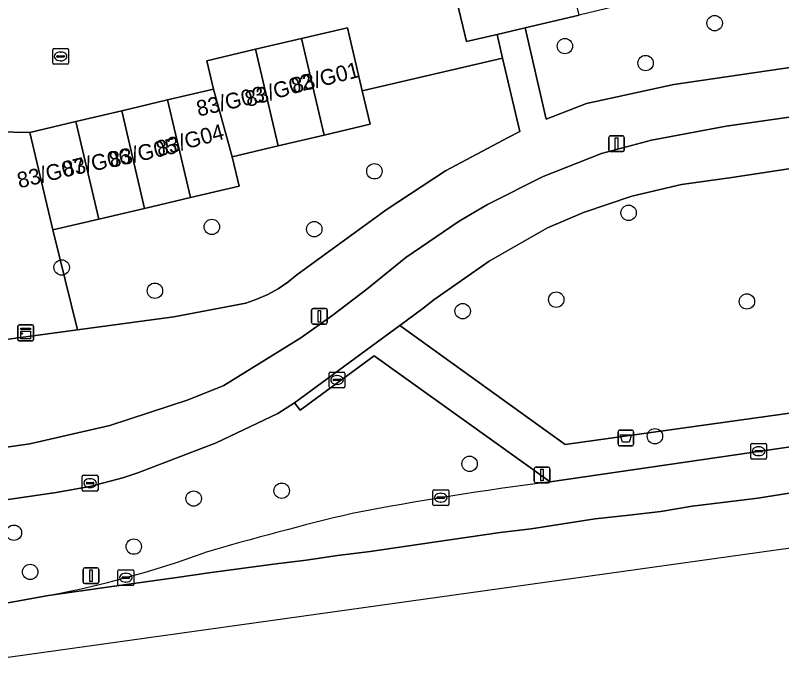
# Model space of a CAD drawing. Extents: x 157793 to 159380, y 380877 to 382313.
# Drawn here: x 158660.5 to 158709.17, y 381159.24 to 381200.11 of the extents above; entities that cross this region are included whole.
import ezdxf

# ---------------------------------------------------------------- set-up
doc = ezdxf.new("R2010")
doc.units = 0
for name, color, linetype in [('IMGEO_Afvalbak', 7, 'Continuous'), ('IMGEO_Berm_groen', 7, 'Continuous'), ('IMGEO_Boom', 7, 'Continuous'), ('IMGEO_Fietspad_gesloten', 7, 'Continuous'), ('IMGEO_Groenvoorziening', 7, 'Continuous'), ('IMGEO_Kast', 7, 'Continuous'), ('IMGEO_Kolk', 7, 'Continuous'), ('IMGEO_Lichtmast', 7, 'Continuous'), ('IMGEO_Pand', 7, 'Continuous'), ('IMGEO_Pand_nummerreeks', 7, 'Continuous'), ('IMGEO_Rijbaan_lokaal_open', 7, 'Continuous'), ('IMGEO_Rijbaan_regionaal_gesloten', 7, 'Continuous'), ('IMGEO_Voetpad_open', 7, 'Continuous')]:
    doc.layers.add(name, color=color, linetype=linetype)

msp = doc.modelspace()

# ---------------------------------------------------------------- linework, layer by layer
at = {"layer": 'IMGEO_Afvalbak'}
for p, q in [((158698.782, 381172.854), (158698.782, 381173.654)), ((158698.782, 381173.654), (158698.782, 381172.854)), ((158698.882, 381173.754), (158699.672, 381173.754)), ((158699.672, 381173.754), (158698.882, 381173.754)), ((158699.772, 381173.654), (158699.772, 381172.854)), ((158699.772, 381172.854), (158699.772, 381173.654)), ((158699.672, 381172.754), (158698.882, 381172.754)), ((158698.882, 381172.754), (158699.672, 381172.754))]:
    msp.add_line(p, q, dxfattribs=at)
msp.add_lwpolyline([(158698.925, 381173.468), (158699.629, 381173.468), (158699.48, 381172.998), (158699.074, 381172.998), (158698.925, 381173.468)], dxfattribs=at)
for centre, start, end in [((158698.882, 381173.654), 90, 180), ((158698.882, 381173.654), 90, 180), ((158699.672, 381173.654), 0, 90), ((158699.672, 381173.654), 360, 90), ((158698.882, 381172.854), 180, 270), ((158698.882, 381172.854), 180, 270), ((158699.672, 381172.854), 270, 0), ((158699.672, 381172.854), 270, 0)]:
    msp.add_arc(centre, 0.1, start, end, dxfattribs=at)
at = {"layer": 'IMGEO_Berm_groen'}
msp.add_lwpolyline([(158728.029, 381190.698), (158727.696, 381193.095), (158726.473, 381192.91), (158724.645, 381192.633), (158706.01, 381189.815), (158702.809, 381189.355), (158699.661, 381188.611), (158696.593, 381187.589), (158694.298, 381186.617), (158690.589, 381184.484), (158687.086, 381182.027), (158686.392, 381181.483), (158684.914, 381180.398), (158695.427, 381172.833), (158714.686, 381175.526), (158714.959, 381175.368), (158715.054, 381174.92), (158722.082, 381175.922), (158725.926, 381180.89), (158729.328, 381181.351)], close=True, dxfattribs=at)
msp.add_lwpolyline([(158694.468, 381170.476), (158683.301, 381178.47), (158678.595, 381175.016), (158678.24, 381175.5), (158677.179, 381174.821), (158673.253, 381172.947), (158668.276, 381171.049), (158667.33, 381170.729), (158665.236, 381170.171), (158663.101, 381169.802), (158659.302, 381169.246), (158656.946, 381168.934), (158658.382, 381162.481), (158662.608, 381163.25)], dxfattribs=at)
for centre, radius, start, end in [((158720.591, 380966.633), 205.51, 97.3027, 100.85619), ((158731.516, 380962.484), 211.876, 103.54752, 106.17714), ((158651.234, 381223.831), 61.639, 280.63332, 290.16825)]:
    msp.add_arc(centre, radius, start, end, dxfattribs=at)
at = {"layer": 'IMGEO_Boom'}
for centre in [(158704.916, 381199.608), (158695.405, 381198.152), (158700.531, 381197.076), (158683.305, 381190.2), (158699.453, 381187.561), (158672.981, 381186.667), (158679.489, 381186.524), (158663.444, 381184.088), (158669.368, 381182.611), (158694.857, 381182.046), (158706.967, 381181.931), (158688.913, 381181.312), (158701.123, 381173.369), (158689.352, 381171.613), (158677.417, 381169.907), (158671.828, 381169.41), (158660.412, 381167.239), (158668.023, 381166.356), (158661.443, 381164.75)]:
    msp.add_circle(centre, 0.489, dxfattribs=at)
at = {"layer": 'IMGEO_Fietspad_gesloten'}
for points in [[(158732.23, 381196.863), (158705.649, 381193.06), (158700.9, 381192.169), (158697.733, 381191.325), (158694.035, 381189.869), (158690.482, 381188.089), (158688.7, 381187.039), (158685.304, 381184.715), (158682.826, 381182.712), (158681.128, 381181.421), (158680.599, 381181.023), (158678.633, 381179.627), (158673.739, 381176.601), (158671.476, 381175.689), (158666.512, 381174.058), (158661.423, 381172.877), (158656.232, 381172.144)], [(158659.302, 381169.246), (158663.101, 381169.802), (158665.236, 381170.171), (158667.33, 381170.729), (158668.276, 381171.049), (158673.253, 381172.947), (158677.179, 381174.821), (158678.24, 381175.5), (158682.788, 381178.838), (158684.914, 381180.398), (158686.392, 381181.483), (158687.086, 381182.027), (158690.589, 381184.484), (158694.298, 381186.617), (158696.593, 381187.589), (158699.661, 381188.611), (158702.809, 381189.355), (158706.01, 381189.815), (158724.645, 381192.633)]]:
    msp.add_lwpolyline(points, dxfattribs=at)
at = {"layer": 'IMGEO_Groenvoorziening'}
msp.add_lwpolyline([(158639.885, 381225.076), (158650.525, 381180.723), (158651.559, 381180.924), (158651.726, 381180.142), (158651.334, 381180.059), (158651.501, 381179.276), (158650.903, 381179.149), (158651.005, 381178.722), (158651.08, 381178.369), (158659.877, 381179.488), (158660.066, 381179.544), (158664.457, 381180.133), (158662.884, 381186.473), (158661.425, 381192.673), (158659.32, 381192.701), (158657.702, 381194.386), (158650.313, 381190.665), (158650.687, 381191.52), (158651.061, 381193.016), (158651.115, 381194.557), (158651.021, 381195.323), (158651.443, 381196.528), (158651.748, 381198.396), (158651.658, 381200.286)], dxfattribs=at)
for points in [[(158722.998, 381202.115), (158718.804, 381201.132), (158717.835, 381205.337), (158696.306, 381200.119), (158692.877, 381199.313), (158694.205, 381193.509), (158696.771, 381194.499), (158702.33, 381195.721), (158723.738, 381198.857)], [(158687.83, 381190.226), (158691.806, 381192.354), (158692.538, 381192.731), (158691.446, 381197.396), (158682.534, 381195.303), (158683.032, 381193.188), (158680.113, 381192.501), (158677.195, 381191.815), (158674.276, 381191.128), (158674.717, 381189.256), (158671.631, 381188.53), (158668.715, 381187.844), (158665.799, 381187.159), (158662.884, 381186.473), (158664.457, 381180.133), (158670.578, 381180.953), (158675.134, 381181.831), (158675.845, 381182.071), (158676.531, 381182.374), (158677.188, 381182.737), (158677.809, 381183.157), (158678.387, 381183.628), (158683.743, 381187.521), (158684.06, 381187.752)]]:
    msp.add_lwpolyline(points, close=True, dxfattribs=at)
at = {"layer": 'IMGEO_Kast'}
for p, q in [((158660.66, 381179.511), (158660.66, 381180.352)), ((158660.66, 381180.352), (158660.66, 381179.511)), ((158660.735, 381180.436), (158661.576, 381180.436)), ((158661.576, 381180.436), (158660.735, 381180.436)), ((158661.66, 381180.361), (158661.66, 381179.52)), ((158661.66, 381179.52), (158661.66, 381180.361)), ((158661.585, 381179.436), (158660.744, 381179.436)), ((158660.744, 381179.436), (158661.585, 381179.436))]:
    msp.add_line(p, q, dxfattribs=at)
for points in [[(158660.855, 381180.226), (158661.455, 381180.226), (158661.455, 381180.141), (158660.855, 381180.141), (158660.855, 381180.226)], [(158660.855, 381180.051), (158661.455, 381180.051), (158661.455, 381179.562), (158660.855, 381179.562), (158660.855, 381180.051)]]:
    msp.add_lwpolyline(points, dxfattribs=at)
msp.add_circle((158660.939, 381179.9), 0.0377, dxfattribs=at)
for centre, start, end in [((158660.738, 381180.358), 92.4484, 184.2845), ((158660.738, 381180.358), 92.4484, 184.2845), ((158661.582, 381180.358), 2.4484, 94.2845), ((158661.582, 381180.358), 2.4484, 94.2845), ((158660.738, 381179.514), 182.4484, 274.2845), ((158660.738, 381179.514), 182.4484, 274.2845), ((158661.582, 381179.514), 272.4484, 4.2845), ((158661.582, 381179.514), 272.4484, 4.2845)]:
    msp.add_arc(centre, 0.0779, start, end, dxfattribs=at)
at = {"layer": 'IMGEO_Kolk'}
for p, q in [((158662.875, 381197.071), (158662.875, 381197.923)), ((158662.95, 381197.997), (158663.802, 381197.997)), ((158663.363, 381197.777), (158663.388, 381197.777)), ((158663.876, 381197.923), (158663.876, 381197.071)), ((158663.134, 381197.491), (158663.134, 381197.503)), ((158663.572, 381197.454), (158663.174, 381197.454)), ((158663.177, 381197.54), (158663.575, 381197.54)), ((158663.386, 381197.217), (158663.361, 381197.217)), ((158663.618, 381197.503), (158663.618, 381197.491)), ((158663.802, 381196.997), (158662.95, 381196.997)), ((158680.431, 381176.516), (158680.431, 381177.368)), ((158680.506, 381177.442), (158681.358, 381177.442)), ((158680.919, 381177.222), (158680.944, 381177.222)), ((158681.432, 381177.368), (158681.432, 381176.516)), ((158680.69, 381176.936), (158680.69, 381176.948)), ((158681.128, 381176.899), (158680.73, 381176.899)), ((158680.733, 381176.985), (158681.131, 381176.985)), ((158681.174, 381176.948), (158681.174, 381176.936)), ((158681.358, 381176.442), (158680.506, 381176.442)), ((158680.942, 381176.662), (158680.917, 381176.662)), ((158707.214, 381171.99), (158707.214, 381172.842)), ((158707.289, 381172.916), (158708.141, 381172.916)), ((158708.215, 381172.842), (158708.215, 381171.99)), ((158707.473, 381172.41), (158707.473, 381172.422)), ((158707.911, 381172.373), (158707.513, 381172.373)), ((158707.516, 381172.459), (158707.914, 381172.459)), ((158707.702, 381172.696), (158707.727, 381172.696)), ((158707.957, 381172.422), (158707.957, 381172.41)), ((158708.141, 381171.916), (158707.289, 381171.916)), ((158707.725, 381172.136), (158707.7, 381172.136)), ((158664.826, 381170.888), (158665.678, 381170.888)), ((158664.751, 381169.962), (158664.751, 381170.814)), ((158665.053, 381170.431), (158665.451, 381170.431)), ((158665.239, 381170.668), (158665.264, 381170.668)), ((158665.752, 381170.814), (158665.752, 381169.962)), ((158665.01, 381170.382), (158665.01, 381170.394)), ((158665.448, 381170.345), (158665.05, 381170.345)), ((158665.262, 381170.108), (158665.237, 381170.108)), ((158665.494, 381170.394), (158665.494, 381170.382)), ((158687.098, 381169.966), (158687.95, 381169.966)), ((158665.678, 381169.888), (158664.826, 381169.888)), ((158687.023, 381169.04), (158687.023, 381169.892)), ((158687.282, 381169.46), (158687.282, 381169.472)), ((158687.325, 381169.509), (158687.723, 381169.509)), ((158687.511, 381169.746), (158687.536, 381169.746)), ((158687.766, 381169.472), (158687.766, 381169.46)), ((158688.024, 381169.892), (158688.024, 381169.04)), ((158687.95, 381168.966), (158687.098, 381168.966)), ((158687.72, 381169.423), (158687.322, 381169.423)), ((158687.534, 381169.186), (158687.509, 381169.186)), ((158667.018, 381163.957), (158667.018, 381164.809)), ((158667.093, 381164.883), (158667.945, 381164.883)), ((158667.506, 381164.663), (158667.531, 381164.663)), ((158668.019, 381164.809), (158668.019, 381163.957)), ((158667.277, 381164.377), (158667.277, 381164.389)), ((158667.715, 381164.34), (158667.317, 381164.34)), ((158667.32, 381164.426), (158667.718, 381164.426)), ((158667.529, 381164.103), (158667.504, 381164.103)), ((158667.761, 381164.389), (158667.761, 381164.377)), ((158667.945, 381163.883), (158667.093, 381163.883))]:
    msp.add_line(p, q, dxfattribs=at)
for points in [[(158662.875, 381197.071), (158662.875, 381197.923)], [(158662.95, 381197.997), (158663.802, 381197.997)], [(158663.876, 381197.923), (158663.876, 381197.071)], [(158663.802, 381196.997), (158662.95, 381196.997)], [(158680.431, 381176.516), (158680.431, 381177.368)], [(158680.506, 381177.442), (158681.358, 381177.442)], [(158681.432, 381177.368), (158681.432, 381176.516)], [(158681.358, 381176.442), (158680.506, 381176.442)], [(158707.214, 381171.99), (158707.214, 381172.842)], [(158707.289, 381172.916), (158708.141, 381172.916)], [(158708.215, 381172.842), (158708.215, 381171.99)], [(158708.141, 381171.916), (158707.289, 381171.916)], [(158664.826, 381170.888), (158665.678, 381170.888)], [(158664.751, 381169.962), (158664.751, 381170.814)], [(158665.752, 381170.814), (158665.752, 381169.962)], [(158687.098, 381169.966), (158687.95, 381169.966)], [(158665.678, 381169.888), (158664.826, 381169.888)], [(158687.023, 381169.04), (158687.023, 381169.892)], [(158688.024, 381169.892), (158688.024, 381169.04)], [(158687.95, 381168.966), (158687.098, 381168.966)], [(158667.018, 381163.957), (158667.018, 381164.809)], [(158667.093, 381164.883), (158667.945, 381164.883)], [(158668.019, 381164.809), (158668.019, 381163.957)], [(158667.945, 381163.883), (158667.093, 381163.883)]]:
    msp.add_lwpolyline(points, dxfattribs=at)
for centre, radius, start, end in [((158662.952, 381197.921), 0.0765, 91.552, 178.448), ((158662.952, 381197.921), 0.0765, 91.552, 178.448), ((158663.8, 381197.921), 0.0765, 1.552, 88.448), ((158663.8, 381197.921), 0.0765, 1.552, 88.448), ((158663.174, 381197.5), 0.0403, 85.8775, 175.7526), ((158663.171, 381197.49), 0.0366, 178.938, 274.7102), ((158663.575, 381197.497), 0.043, 264.8664, 352.4533), ((158663.579, 381197.502), 0.0386, 1.7309, 96.639), ((158662.952, 381197.073), 0.0765, 181.552, 268.448), ((158662.952, 381197.073), 0.0765, 181.552, 268.448), ((158663.8, 381197.073), 0.0765, 271.552, 358.448), ((158663.8, 381197.073), 0.0765, 271.552, 358.448), ((158680.508, 381177.366), 0.0765, 91.552, 178.448), ((158680.508, 381177.366), 0.0765, 91.552, 178.448), ((158681.356, 381177.366), 0.0765, 1.552, 88.448), ((158681.356, 381177.366), 0.0765, 1.552, 88.448), ((158680.73, 381176.945), 0.0403, 85.8775, 175.7526), ((158680.727, 381176.935), 0.0366, 178.938, 274.7102), ((158681.131, 381176.942), 0.043, 264.8664, 352.4533), ((158681.135, 381176.947), 0.0386, 1.7309, 96.639), ((158680.508, 381176.518), 0.0765, 181.552, 268.448), ((158680.508, 381176.518), 0.0765, 181.552, 268.448), ((158681.356, 381176.518), 0.0765, 271.552, 358.448), ((158681.356, 381176.518), 0.0765, 271.552, 358.448), ((158707.291, 381172.84), 0.0765, 91.552, 178.448), ((158707.291, 381172.84), 0.0765, 91.552, 178.448), ((158708.139, 381172.84), 0.0765, 1.552, 88.448), ((158708.139, 381172.84), 0.0765, 1.552, 88.448), ((158707.513, 381172.419), 0.0403, 85.8775, 175.7526), ((158707.51, 381172.409), 0.0366, 178.938, 274.7102), ((158707.914, 381172.416), 0.043, 264.8664, 352.4533), ((158707.918, 381172.421), 0.0386, 1.7309, 96.639), ((158707.291, 381171.992), 0.0765, 181.552, 268.448), ((158707.291, 381171.992), 0.0765, 181.552, 268.448), ((158708.139, 381171.992), 0.0765, 271.552, 358.448), ((158708.139, 381171.992), 0.0765, 271.552, 358.448), ((158664.828, 381170.812), 0.0765, 91.552, 178.448), ((158664.828, 381170.812), 0.0765, 91.552, 178.448), ((158665.676, 381170.812), 0.0765, 1.552, 88.448), ((158665.676, 381170.812), 0.0765, 1.552, 88.448), ((158665.05, 381170.391), 0.0403, 85.8775, 175.7526), ((158665.455, 381170.393), 0.0386, 1.7309, 96.639), ((158664.828, 381169.964), 0.0765, 181.552, 268.448), ((158664.828, 381169.964), 0.0765, 181.552, 268.448), ((158665.047, 381170.381), 0.0366, 178.938, 274.7102), ((158665.451, 381170.388), 0.043, 264.8664, 352.4533), ((158665.676, 381169.964), 0.0765, 271.552, 358.448), ((158665.676, 381169.964), 0.0765, 271.552, 358.448), ((158687.1, 381169.89), 0.0765, 91.552, 178.448), ((158687.1, 381169.89), 0.0765, 91.552, 178.448), ((158687.948, 381169.89), 0.0765, 1.552, 88.448), ((158687.948, 381169.89), 0.0765, 1.552, 88.448), ((158687.322, 381169.469), 0.0403, 85.8775, 175.7526), ((158687.319, 381169.459), 0.0366, 178.938, 274.7102), ((158687.723, 381169.466), 0.043, 264.8664, 352.4533), ((158687.727, 381169.471), 0.0386, 1.7309, 96.639), ((158687.1, 381169.042), 0.0765, 181.552, 268.448), ((158687.1, 381169.042), 0.0765, 181.552, 268.448), ((158687.948, 381169.042), 0.0765, 271.552, 358.448), ((158687.948, 381169.042), 0.0765, 271.552, 358.448), ((158667.095, 381164.807), 0.0765, 91.552, 178.448), ((158667.095, 381164.807), 0.0765, 91.552, 178.448), ((158667.943, 381164.807), 0.0765, 1.552, 88.448), ((158667.943, 381164.807), 0.0765, 1.552, 88.448), ((158667.317, 381164.386), 0.0403, 85.8775, 175.7526), ((158667.314, 381164.376), 0.0366, 178.938, 274.7102), ((158667.718, 381164.383), 0.043, 264.8664, 352.4533), ((158667.722, 381164.388), 0.0386, 1.7309, 96.639), ((158667.095, 381163.959), 0.0765, 181.552, 268.448), ((158667.095, 381163.959), 0.0765, 181.552, 268.448), ((158667.943, 381163.959), 0.0765, 271.552, 358.448), ((158667.943, 381163.959), 0.0765, 271.552, 358.448)]:
    msp.add_arc(centre, radius, start, end, dxfattribs=at)
for centre, major_axis, ratio, start_param, end_param in [((158663.362, 381197.497), (-0.387, 0.002), 0.722429, 4.712389, 7.853982), ((158663.387, 381197.497), (-0.39, 0.002), 0.717154, 1.570796, 4.712389), ((158680.918, 381176.942), (-0.387, 0.002), 0.722429, 4.712389, 7.853982), ((158680.943, 381176.942), (-0.39, 0.002), 0.717154, 1.570796, 4.712389), ((158707.701, 381172.416), (-0.387, 0.002), 0.722429, 4.712389, 7.853982), ((158707.726, 381172.416), (-0.39, 0.002), 0.717154, 1.570796, 4.712389), ((158665.238, 381170.388), (-0.387, 0.002), 0.722429, 4.712389, 7.853982), ((158665.263, 381170.388), (-0.39, 0.002), 0.717154, 1.570796, 4.712389), ((158687.51, 381169.466), (-0.387, 0.002), 0.722429, 4.712389, 7.853982), ((158687.535, 381169.466), (-0.39, 0.002), 0.717154, 1.570796, 4.712389), ((158667.505, 381164.383), (-0.387, 0.002), 0.722429, 4.712389, 7.853982), ((158667.53, 381164.383), (-0.39, 0.002), 0.717154, 1.570796, 4.712389)]:
    msp.add_ellipse(centre, major_axis=major_axis, ratio=ratio, start_param=start_param, end_param=end_param, dxfattribs=at)
at = {"layer": 'IMGEO_Lichtmast'}
for p, q in [((158698.187, 381191.55), (158698.187, 381192.35)), ((158698.187, 381192.35), (158698.187, 381191.55)), ((158698.287, 381192.45), (158699.077, 381192.45)), ((158699.077, 381192.45), (158698.287, 381192.45)), ((158699.177, 381192.35), (158699.177, 381191.55)), ((158699.177, 381191.55), (158699.177, 381192.35)), ((158699.077, 381191.45), (158698.287, 381191.45)), ((158698.287, 381191.45), (158699.077, 381191.45)), ((158679.315, 381180.588), (158679.315, 381181.388)), ((158679.315, 381181.388), (158679.315, 381180.588)), ((158679.415, 381181.488), (158680.205, 381181.488)), ((158680.205, 381181.488), (158679.415, 381181.488)), ((158680.305, 381181.388), (158680.305, 381180.588)), ((158680.305, 381180.588), (158680.305, 381181.388)), ((158680.205, 381180.488), (158679.415, 381180.488)), ((158679.415, 381180.488), (158680.205, 381180.488)), ((158693.56, 381171.406), (158694.35, 381171.406)), ((158694.35, 381171.406), (158693.56, 381171.406)), ((158693.46, 381170.506), (158693.46, 381171.306)), ((158693.46, 381171.306), (158693.46, 381170.506)), ((158694.45, 381171.306), (158694.45, 381170.506)), ((158694.45, 381170.506), (158694.45, 381171.306)), ((158694.35, 381170.406), (158693.56, 381170.406)), ((158693.56, 381170.406), (158694.35, 381170.406)), ((158664.81, 381164.107), (158664.81, 381164.907)), ((158664.81, 381164.907), (158664.81, 381164.107)), ((158664.91, 381165.007), (158665.7, 381165.007)), ((158665.7, 381165.007), (158664.91, 381165.007)), ((158665.8, 381164.907), (158665.8, 381164.107)), ((158665.8, 381164.107), (158665.8, 381164.907)), ((158665.7, 381164.007), (158664.91, 381164.007)), ((158664.91, 381164.007), (158665.7, 381164.007))]:
    msp.add_line(p, q, dxfattribs=at)
for points in [[(158698.607, 381192.325), (158698.757, 381192.325), (158698.757, 381191.575), (158698.607, 381191.575), (158698.607, 381192.325)], [(158679.735, 381181.363), (158679.885, 381181.363), (158679.885, 381180.613), (158679.735, 381180.613), (158679.735, 381181.363)], [(158693.88, 381171.281), (158694.03, 381171.281), (158694.03, 381170.531), (158693.88, 381170.531), (158693.88, 381171.281)], [(158665.23, 381164.882), (158665.38, 381164.882), (158665.38, 381164.132), (158665.23, 381164.132), (158665.23, 381164.882)]]:
    msp.add_lwpolyline(points, dxfattribs=at)
for centre, start, end in [((158698.287, 381192.35), 90, 180), ((158698.287, 381192.35), 90, 180), ((158699.077, 381192.35), 0, 90), ((158699.077, 381192.35), 360, 90), ((158698.287, 381191.55), 180, 270), ((158698.287, 381191.55), 180, 270), ((158699.077, 381191.55), 270, 0), ((158699.077, 381191.55), 270, 0), ((158679.415, 381181.388), 90, 180), ((158679.415, 381181.388), 90, 180), ((158680.205, 381181.388), 0, 90), ((158680.205, 381181.388), 360, 90), ((158679.415, 381180.588), 180, 270), ((158679.415, 381180.588), 180, 270), ((158680.205, 381180.588), 270, 0), ((158680.205, 381180.588), 270, 0), ((158693.56, 381171.306), 90, 180), ((158693.56, 381171.306), 90, 180), ((158694.35, 381171.306), 0, 90), ((158694.35, 381171.306), 360, 90), ((158693.56, 381170.506), 180, 270), ((158693.56, 381170.506), 180, 270), ((158694.35, 381170.506), 270, 0), ((158694.35, 381170.506), 270, 0), ((158664.91, 381164.907), 90, 180), ((158664.91, 381164.907), 90, 180), ((158665.7, 381164.907), 0, 90), ((158665.7, 381164.907), 360, 90), ((158664.91, 381164.107), 180, 270), ((158664.91, 381164.107), 180, 270), ((158665.7, 381164.107), 270, 0), ((158665.7, 381164.107), 270, 0)]:
    msp.add_arc(centre, 0.1, start, end, dxfattribs=at)
at = {"layer": 'IMGEO_Pand'}
for points in [[(158688.441, 381201.468), (158689.154, 381198.437), (158691.097, 381198.894), (158692.877, 381199.313), (158696.306, 381200.119), (158695.593, 381203.15)], [(158678.67, 381198.636), (158680.113, 381192.501), (158683.032, 381193.188), (158682.534, 381195.303), (158681.589, 381199.323)], [(158677.195, 381191.815), (158680.113, 381192.501), (158678.67, 381198.636), (158675.751, 381197.95)], [(158677.195, 381191.815), (158675.751, 381197.95), (158672.662, 381197.223), (158673.087, 381195.417), (158674.276, 381191.128)], [(158670.172, 381194.731), (158671.631, 381188.53), (158674.717, 381189.256), (158674.276, 381191.128), (158673.087, 381195.417)], [(158670.172, 381194.731), (158667.256, 381194.045), (158668.715, 381187.844), (158671.631, 381188.53)], [(158668.715, 381187.844), (158667.256, 381194.045), (158664.34, 381193.359), (158665.799, 381187.159)], [(158665.799, 381187.159), (158664.34, 381193.359), (158661.425, 381192.673), (158662.884, 381186.473)]]:
    msp.add_lwpolyline(points, close=True, dxfattribs=at)
at = {"layer": 'IMGEO_Rijbaan_lokaal_open'}
msp.add_lwpolyline([(158655.652, 381200.253), (158656.869, 381195.254), (158657.702, 381194.386), (158659.32, 381192.701), (158661.425, 381192.673), (158664.34, 381193.359), (158667.256, 381194.045), (158670.172, 381194.731), (158673.087, 381195.417), (158672.662, 381197.223), (158675.751, 381197.95), (158678.67, 381198.636), (158681.589, 381199.323), (158682.534, 381195.303), (158691.446, 381197.396), (158691.097, 381198.894), (158689.154, 381198.437), (158688.441, 381201.468)], dxfattribs=at)
at = {"layer": 'IMGEO_Rijbaan_regionaal_gesloten'}
for points in [[(158709.658, 381169.744), (158707.667, 381169.437), (158705.579, 381169.186), (158703.491, 381168.936), (158701.5, 381168.586), (158699.492, 381168.359), (158697.338, 381168.114), (158695.302, 381167.798), (158693.267, 381167.482), (158691.3, 381167.254), (158687.077, 381166.64), (158683.029, 381166.051), (158680.972, 381165.802), (158678.976, 381165.503), (158676.908, 381165.247), (158674.844, 381164.965), (158672.78, 381164.683), (158670.763, 381164.387), (158668.618, 381164.094), (158666.473, 381163.8), (158662.608, 381163.25), (158658.382, 381162.481), (158659.254, 381159.237), (158811.548, 381180.518)], [(158726.404, 381172.535), (158722.227, 381174.512), (158694.468, 381170.476)], [(158662.608, 381163.25), (158666.473, 381163.8), (158668.618, 381164.094), (158670.763, 381164.387), (158672.78, 381164.683), (158674.844, 381164.965), (158676.908, 381165.247), (158678.976, 381165.503), (158680.972, 381165.802), (158683.029, 381166.051), (158687.077, 381166.64), (158691.3, 381167.254), (158693.267, 381167.482), (158695.302, 381167.798), (158697.338, 381168.114), (158699.492, 381168.359), (158701.5, 381168.586), (158703.491, 381168.936), (158705.579, 381169.186), (158707.667, 381169.437), (158709.658, 381169.744)]]:
    msp.add_lwpolyline(points, dxfattribs=at)
for centre, radius, start, end in [((158720.591, 380966.633), 205.51, 97.3027, 100.85619), ((158731.516, 380962.484), 211.876, 103.54752, 106.17714), ((158651.234, 381223.831), 61.639, 280.63332, 290.16825)]:
    msp.add_arc(centre, radius, start, end, dxfattribs=at)
at = {"layer": 'IMGEO_Voetpad_open'}
for points in [[(158723.738, 381198.857), (158702.33, 381195.721), (158696.771, 381194.499), (158694.205, 381193.509), (158692.877, 381199.313), (158691.097, 381198.894), (158691.446, 381197.396), (158692.538, 381192.731), (158691.806, 381192.354), (158687.83, 381190.226), (158684.06, 381187.752), (158683.743, 381187.521), (158678.387, 381183.628), (158677.809, 381183.157), (158677.188, 381182.737), (158676.531, 381182.374), (158675.845, 381182.071), (158675.134, 381181.831), (158670.578, 381180.953), (158664.457, 381180.133), (158660.066, 381179.544)], [(158656.232, 381172.144), (158661.423, 381172.877), (158666.512, 381174.058), (158671.476, 381175.689), (158673.739, 381176.601), (158678.633, 381179.627), (158680.599, 381181.023), (158681.128, 381181.421), (158682.826, 381182.712), (158685.304, 381184.715), (158688.7, 381187.039), (158690.482, 381188.089), (158694.035, 381189.869), (158697.733, 381191.325), (158700.9, 381192.169), (158705.649, 381193.06), (158732.23, 381196.863)], [(158740.526, 381194.919), (158739.479, 381194.775), (158729.032, 381193.297), (158727.696, 381193.095), (158728.029, 381190.698), (158729.328, 381181.351), (158725.926, 381180.89), (158722.082, 381175.922), (158715.054, 381174.92), (158714.959, 381175.368), (158714.686, 381175.526), (158695.427, 381172.833), (158684.914, 381180.398), (158682.788, 381178.838), (158678.24, 381175.5), (158678.595, 381175.016), (158683.301, 381178.47), (158694.468, 381170.476), (158722.227, 381174.512)]]:
    msp.add_lwpolyline(points, dxfattribs=at)

# ---------------------------------------------------------------- texts
at = {"layer": 'IMGEO_Pand_nummerreeks'}
for s, rotation, p in [('83/G01', 14.1911, (158678.178, 381195.128)), ('83/G02', 16.2324, (158675.259, 381194.267)), ('83/G03', 12.9946, (158672.13, 381193.672)), ('83/G04', 15.141, (158669.6, 381191.122)), ('83/G05', 12.8043, (158666.579, 381190.41)), ('83/G06', 11.9207, (158663.607, 381189.817)), ('83/G07', 13.5704, (158660.753, 381189.111))]:
    msp.add_text(s, height=1, rotation=rotation, dxfattribs=at).set_placement(p)

doc.saveas('drawing.dxf')
